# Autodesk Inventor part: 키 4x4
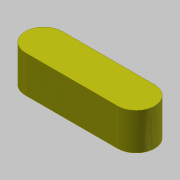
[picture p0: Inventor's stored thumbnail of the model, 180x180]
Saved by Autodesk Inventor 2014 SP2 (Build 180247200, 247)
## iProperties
Created: 2018-09
Part Number: 키 4x4
Document SubType Name: Modeling
Density: 1 g/cm^3
Material: 강철, 연강
Appearance: 노란색
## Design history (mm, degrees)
sketch "스케치1"
  geometry: L1 (-5, -2)-(5, -2); L2 (5, 2)-(-5, 2); A1 r 2 centre (5, 0) between (5, -2) and (5, 2); A2 r 2 centre (-5, 0) between (-5, 2) and (-5, -2); 2 further points
  constraints: 4 end point, 4 point on circle, 4 tangent, 2 centre point, 1 horizontal, 1 horizontal alignment, 1 midpoint, 1 parallel, 1 vertical alignment
  dimensions: "d0" = 4 distance between parallel lines of L1 L2; "d1" = 14 dimension on A1 A2
extrude "돌출1" new body sketch "스케치1" stored distance "d2" = 4; taper "d3" = 0 deg
node "솔리드1"
